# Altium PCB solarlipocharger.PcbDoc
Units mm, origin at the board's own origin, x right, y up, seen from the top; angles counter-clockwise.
Board outline 52.7 x 22.73 mm, 2 copper layers (Top Layer, Bottom Layer); 23 components, 15 nets, 70 pads, 27 vias.
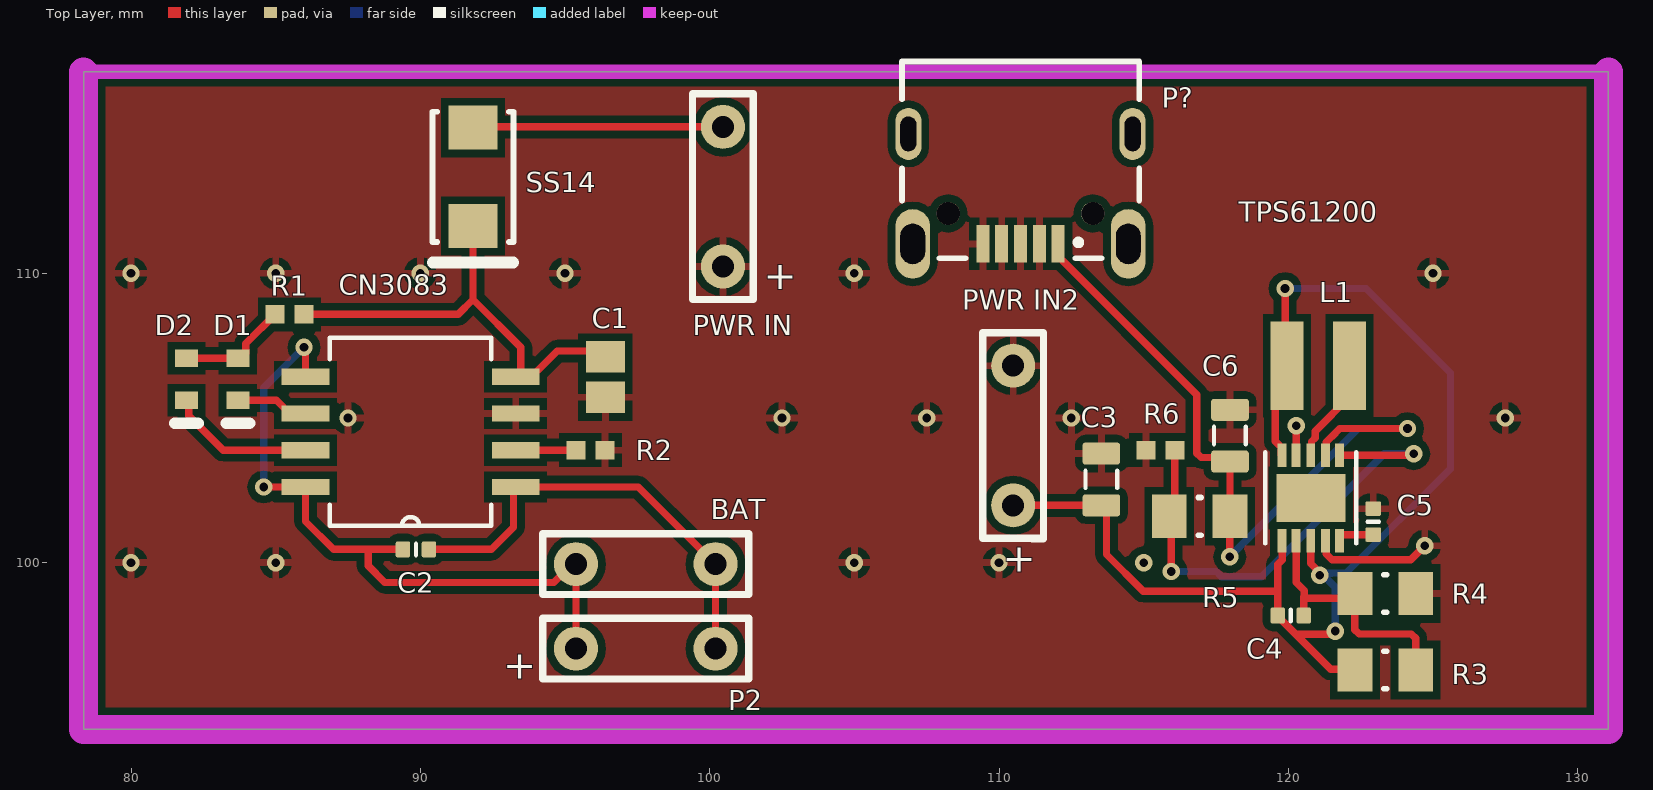
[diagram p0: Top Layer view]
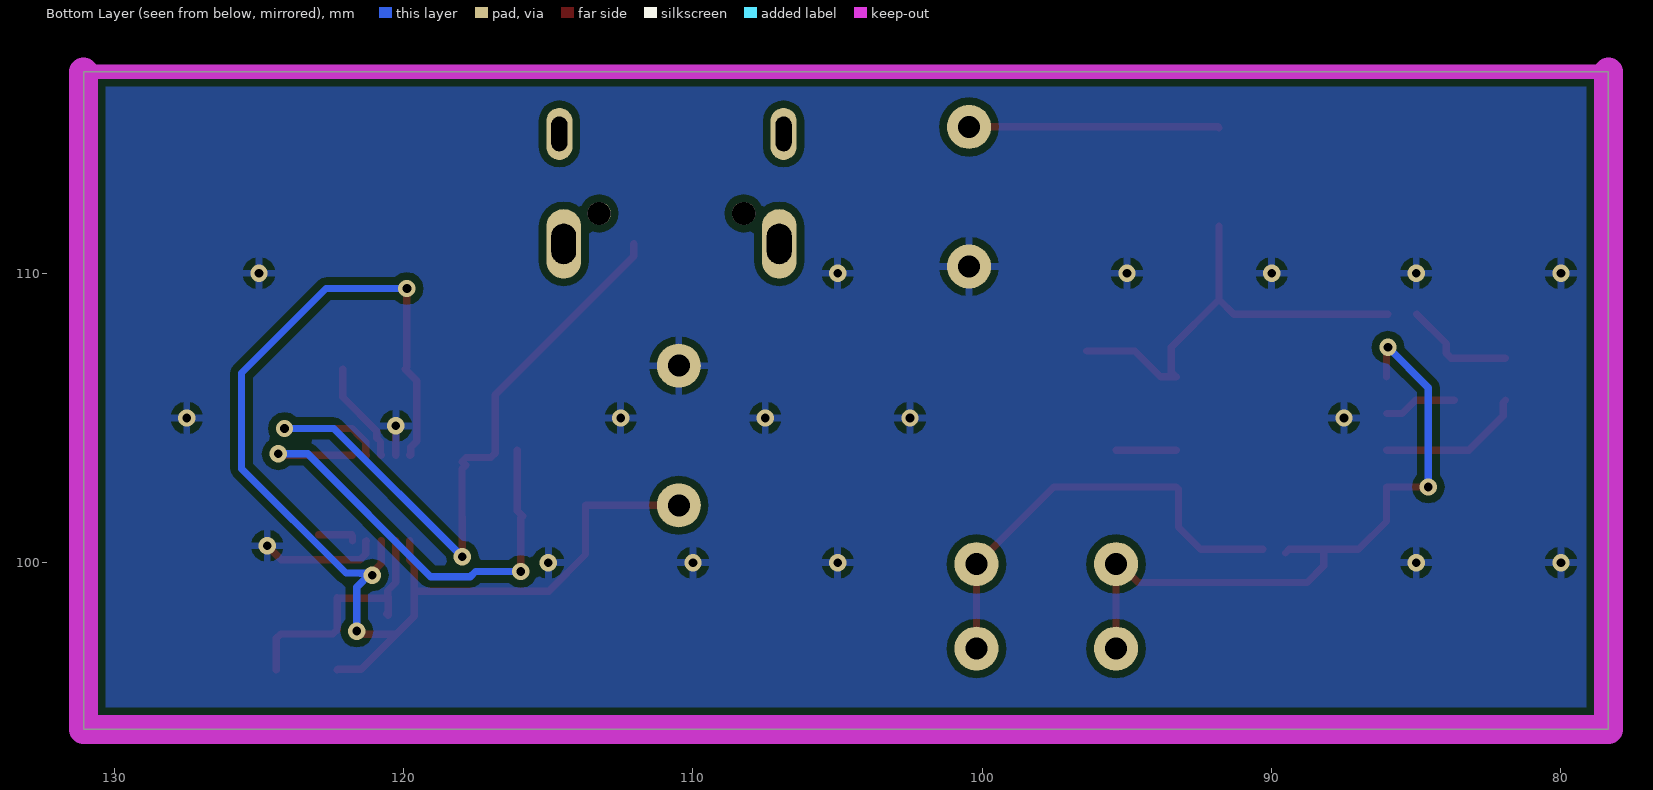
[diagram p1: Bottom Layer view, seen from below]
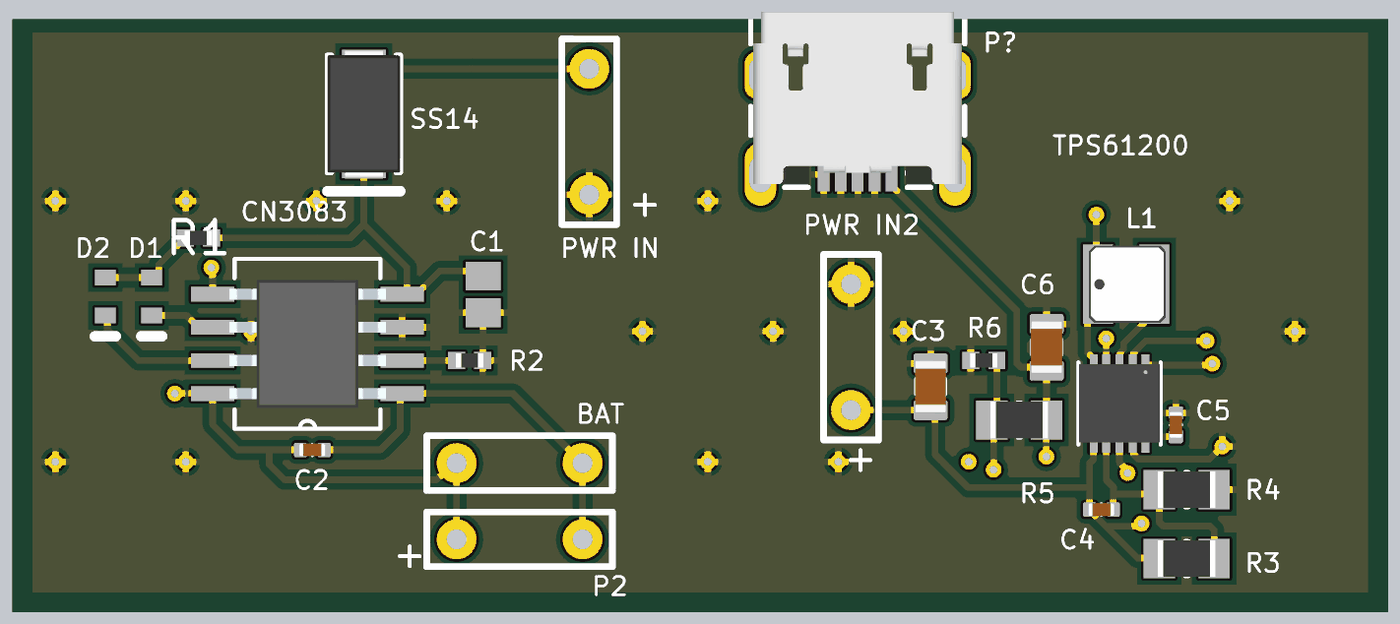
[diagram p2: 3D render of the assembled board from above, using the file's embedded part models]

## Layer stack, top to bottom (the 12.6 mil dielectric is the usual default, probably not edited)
Top Solder: solder mask 0.0102, Solder Resist, Dk 3.5
Top Layer: signal copper 0.0356
Dielectric 1: dielectric 0.32, FR-4, Dk 4.8
Bottom Layer: signal copper 0.0356
Bottom Solder: solder mask 0.0102, Solder Resist, Dk 3.5

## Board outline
78.359,94.234 131.064,94.234 131.064,116.967 78.359,116.967

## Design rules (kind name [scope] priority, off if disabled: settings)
Clearance [All] p1: gap=0.254 ignorepadtopadclearanceinfootprint=FALSE except(0: Arc-Hole Track-Hole SMDPad-Hole THPad-Hole Via-Hole Fill-Hole Poly-Hole Region-Hole Text-Hole; 0.127: Arc-Arc Arc-Track Arc-SMDPad Track-Track Track-SMDPad SMDPad-SMDPad)
PolygonConnect [All] p1: connectstyle=Relief reliefconductorwidth=0.254 reliefentries=4 polygonreliefangle="90 Angle" airgapwidth=0.254
RoutingVias [All] p1: holewidth=0.3 width=1.27 viastyle="Through Hole" minholewidth=0.3 minwidth=0.6 maxholewidth=0.711 maxwidth=0.6
SolderMaskExpansion [All] p1: expansion=0.102 istentingtop=FALSE
Width [All] p1: maxlimit=0.254 minlimit=0.254 preferedwidth=0.254
30 further rules are at their usual default settings.

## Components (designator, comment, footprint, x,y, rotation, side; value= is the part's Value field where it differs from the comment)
BAT "BAT" PWR 97.79,99.949 r0 top
C1 "08056D226MAT2A" CAPC2013X140X50LL20T25 96.393,106.415 r270 top
C2 "4.7 uF" "CAPACITOR 0402" 89.847,100.457 r0 top
C3 "10 uF" "CAPACITOR 0805" 113.538,102.881 r90 top
C4 "0.1 uF" "CAPACITOR 0402" 120.084,98.171 r0 top
C5 "0.1 uF" "CAPACITOR 0402" 122.936,101.415 r90 top
C6 "22 uF" "CAPACITOR 0805" 117.983,104.393 r90 top
CN3083 "CN3038" CN3083 89.662,104.648 r180 top
D1 "GREEN" "DIODE 0603" 83.693,106.336 r270 top
D2 "RED" "DIODE 0603" 81.915,106.336 r270 top
L1 "4.7 uF 1.2A" LPS3015 121.031,106.807 r0 top
P2 "PWR OUT" PWR 97.79,97.028 r0 top
P? "MICRO USB  PORT" "MICRO USB OUT" 110.744,114.173 r180 top
"PWR IN" "SOLAR PWR IN" PWR 100.457,112.649 r270 top
"PWR IN2" "BAT IN" PWR 110.49,104.394 r90 top
R1 "330" "RESISTOR 0402" 85.479,108.585 r180 top
R2 "3.6k" "RESISTOR 0402" 95.877,103.886 r0 top
R3 "2M" "RESISTOR 0805" 123.351,96.289 r0 top
R4 "220k" "RESISTOR 0805" 123.351,98.933 r0 top
R5 "1.2M" "RESISTOR 0805" 116.933,101.6 r180 top
R6 "220k" "RESISTOR 0402" 115.578,103.886 r180 top
SS14 "SS14 Diode" SS14 91.827,113.345 r270 top
TPS61200 "TPS61200" TPS61200 120.777,102.235 r270 top

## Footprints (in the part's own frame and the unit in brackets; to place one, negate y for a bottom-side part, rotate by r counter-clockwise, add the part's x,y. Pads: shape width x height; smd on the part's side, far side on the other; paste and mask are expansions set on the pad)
"CAPACITOR 0402" [mm]
  rrect25% 0.5x0.55 smd: 1(-0.45,0) 2(0.45,0)
  silkscreen extent 0,-0.2 0,0.2, body extent -0.5,-0.25 0.5,0.25, height 0.6
"CAPACITOR 0805" [mm]
  rrect25% 0.76x1.3 smd: 1(-0.9,0) 2(0.89,0)
  silkscreen extent -0.3,-0.55 0.3,0.55, body extent -1,-0.6 1,0.6, height 1.45
CAPC2013X140X50LL20T25 [mm] "Chip Capacitor, 2-Leads, Body 2.00x1.25mm, IPC High Density"
  rect 1.1x1.35 smd: 1(-0.7,0) 2(0.7,0)
  body extent -1.1,-0.72 1.1,0.72, height 1.4
CN3083 [mil]
  rect 65x22 smd: 1(-143,80) 2(-143,30) 3(-143,-20) 4(-143,-70) 5(143,-70) 6(143,-20) 7(143,30) 8(143,80)
  silkscreen extent -110,-123 110,133, body extent -118,-91 118,101, height 69
"DIODE 0603" [mm]
  rect 0.6x0.8 smd: 1(-0.725,0) 2(0.725,0)
  silkscreen extent 1.53,-0.4 1.53,0.4, body extent -0.8,-0.4 0.8,0.4, height 0.65
LPS3015 [mm]
  rect 1.14x3.05 smd: 1(-1.08,0) 2(1.08,0)
  body extent -1.43,-1.47 1.52,1.47, height 1.4
"MICRO USB OUT" [mm]
  rect 0.45x1.3 smd: 1(-1.3,3.154) 2(-0.65,3.154) 3(0,3.154) 4(0.65,3.154) 5(1.3,3.154)
  oval 1.2x2.4 hole 0.85 slot 1.4 at 90 deg: S1(-3.725,3.154) S2(3.725,3.154)
  oval 0.9x1.8 hole 0.55 slot 1.2 at 90 deg: S3(3.875,-0.646) S4(-3.875,-0.646)
  round 0.8 hole 0.8 unplated: ""(-2.5,2.104) ""(2.5,2.104)
  silkscreen extent -4.1,-3.15 4.1,3.65, body extent -4,-3.06 4,3.54, height 1.67
PWR [mil]
  round 60 hole 30: 1(-95,0) 2(95,0)
  silkscreen extent -140,-41 140,41
"RESISTOR 0402" [mm]
  rect 0.65x0.65 smd: 1(-0.5,0) 2(0.5,0)
  body extent -0.53,-0.28 0.53,0.28, height 0.4
"RESISTOR 0805" [mm]
  rect 1.2x1.5 smd: 1(-1.05,0) 2(1.05,0)
  silkscreen extent -0.05,-0.65 0.05,0.65, body extent -1.1,-0.7 1.1,0.7, height 0.5
SS14 [mm]
  rect 1.52x1.68 smd: 1(-1.688,-0.006) 2(1.712,-0.006)
  silkscreen extent -2.24,-1.41 2.97,1.39, body extent -2.46,-1.4 2.48,1.39, height 2.29
TPS61200 [mil]
  rect 32x12 smd: 1(-58,39) 2(-58,20) 3(-58,0) 4(-58,-20) 5(-58,-39) 6(58,-39) 7(58,-20) 8(58,0) 9(58,20) 10(58,39)
  rect 65x94 smd: 11(0,0)
  silkscreen extent -62,-62 62,62, body extent -59,-61 59,61, height 39

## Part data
C1: library part CMP-001-00083-1, "AVX         08056D226MAT2A.            CERAMIC CAPACITOR, 22UF, 6.3V, X5R, 20%, 0805, FULL REEL", Capacitance=22uF, Case Code (Imperial)=0805, Case Code (Metric)=2012, Dielectric=X5R, Dielectric Material=Ceramic, Insulation Resistance=10GR, Max Operating Temperature=85°C, Min Operating Temperature=-55°C, Package Quantity=1, Tolerance=20%, Voltage=6.3V
C2 C4 C5: library part "Capacitor 0402"
C3 C6: library part "Capacitor 0805"
D1 D2: library part "Diode 0603"
L1: library part Inductor, "LPS3015 - 222MRB"
"PWR IN2": library part "SOLAR PWR IN"
R1 R2 R6: library part "Resistor 0402"
R3 R4 R5: library part "Resistor 0805"

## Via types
v1: diameter 0.6, hole 0.3, Top Layer to Bottom Layer, 27 vias

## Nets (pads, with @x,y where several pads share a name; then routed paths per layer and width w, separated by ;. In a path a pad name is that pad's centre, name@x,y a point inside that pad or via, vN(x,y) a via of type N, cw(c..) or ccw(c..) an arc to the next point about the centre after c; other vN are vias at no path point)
GND: "PWR IN2.2" "PWR IN.2" C1.2 C3.2 C5.2 C6.2 CN3083.3 P?.2 P?.3 P?.4 P?.5 R2.2 R4.2 R6.2 TPS61200.4 TPS61200.9 | length 5.2
  Top Layer w0.254: TPS61200.4 v1(120.269,104.728) ; TPS61200.9 121.31,100.736 121.31,100.301 121.51,100.101 124.231,100.101 v1(124.714,100.584)
  other v1: 80,100 85,100 105,100 110,100 115,100 87.5,105 102.5,105 107.5,105 112.5,105 127.5,105 80,110 85,110 90,110 95,110 105,110 125,110
NetBAT_1: BAT.1 C2.1 CN3083.5 CN3083.8 P2.1 | length 24.2
  Top Layer w0.254: v1(84.582,102.616) CN3083.8 86.03,101.422 86.995,100.457 88.196,100.457 ; v1(85.979,107.442) 86.03,107.391 CN3083.5 ; C2.1@89.52,100.334 C2.1 88.196,100.457 ; P2.1 BAT.1 95.241,99.949 94.606,99.314 88.773,99.314 88.196,99.891 88.196,100.457
  Bottom Layer w0.254: v1(84.582,102.616) 84.582,106.045 v1(85.979,107.442)
NetBAT_2: BAT.2 C2.2 CN3083.1 P2.2 | length 15.6
  Top Layer w0.254: C2.2 92.456,100.457 93.218,101.219 93.218,102.54 CN3083.1 97.536,102.616 BAT.2 P2.2
NetC1_1: C1.1 CN3083.4 R1.1 SS14.2 | length 15.5
  Top Layer w0.254: R1.1 91.313,108.585 91.821,109.093 ; SS14.2 91.821,109.093 ; CN3083.4 CN3083.4@93.32,106.426 ; C1.1@96.393,107.315 94.729,107.315 93.84,106.426 CN3083.4@93.32,106.426 ; 91.821,109.093 93.472,107.442 93.472,106.578 CN3083.4@93.32,106.426
NetC3_1: "PWR IN2.1" C3.1 C4.1 L1.1 R3.1 TPS61200.5 TPS61200.6 TPS61200.8 | length 44.7
  Top Layer w0.254: 110.49,101.981 113.713,101.981 113.713,100.282 114.981,99.014 119.634,99.014 ; TPS61200.6 119.786,100.101 119.634,99.949 119.634,99.014 ; TPS61200.5 119.761,103.734 119.761,103.988 119.552,104.197 119.552,106.281 119.951,106.68 119.888,106.743 v1(119.888,109.474) ; TPS61200.8 120.777,99.971 121.087,99.661 v1(121.087,99.568) ; v1(121.622,97.635) 121.556,97.568 121.444,97.568 121.405,97.529 120.251,97.529 ; R3.1 122.279,96.311 121.469,96.311 120.251,97.529 ; 119.634,99.014 C4.1 119.634,98.146 120.251,97.529
  Bottom Layer w0.254: v1(119.888,109.474) 122.682,109.474 125.603,106.553 125.603,103.251 121.995,99.643 121.514,99.643 121.505,99.634 121.153,99.634 v1(121.087,99.568) ; v1@121.147,99.63 121.622,99.155 v1(121.622,97.635)
NetC4_2: C4.2 R3.2 R4.1 TPS61200.7 | length 9
  Top Layer w0.254: TPS61200.7 120.269,99.314 120.545,99.038 120.545,98.828 120.534,98.817 120.534,98.767 ; C4.2@120.595,98.232 C4.2 120.534,98.767 ; R3.2 124.401,97.387 124.252,97.536 122.45,97.536 122.301,97.685 122.301,98.783 122.285,98.767 120.534,98.767
NetC5_1: C5.1 TPS61200.10 | length 1.4
  Top Layer w0.254: TPS61200.10 121.768,100.94 121.793,100.965 C5.1
NetC6_1: C6.1 P?.1 R5.1 TPS61200.2 | length 25.2
  Top Layer w0.254: P?.1 112.044,110.594 116.84,105.798 116.84,103.781 116.989,103.632 117.844,103.632 C6.1 ; C6.1@117.856,103.366 117.983,103.24 R5.1 117.975,101.592 v1(117.975,100.198) ; TPS61200.2 121.31,103.734 121.31,104.169 121.51,104.369 121.514,104.369 121.779,104.634 v1(124.117,104.634)
  Bottom Layer w0.254: v1(117.975,100.198) 122.411,104.634 v1(124.117,104.634)
NetCN3083_2: CN3083.2 R2.1 | length 2.1
  Top Layer w0.254: CN3083.2 R2.1
NetCN3083_6: CN3083.6 D1.2 | length 2.5
  Top Layer w0.254: D1.2 85.029,105.611 85.484,105.156 CN3083.6
NetCN3083_7: CN3083.7 D2.2 | length 5.1
  Top Layer w0.254: D2.2 81.992,105.534 81.992,105.079 83.185,103.886 CN3083.7
NetD1_1: D1.1 D2.1 R1.2 | length 3.9
  Top Layer w0.254: D2.1 D1.1 83.793,107.061 83.966,107.234 83.966,107.572 R1.2
NetL1_2: L1.2 TPS61200.3 | length 3.5
  Top Layer w0.254: TPS61200.3 120.802,103.734 120.802,104.189 120.932,104.319 120.932,104.546 122.111,105.725 L1.2@122.111,106.68
"NetPWR IN_1": "PWR IN.1" SS14.1 | length 8.6
  Top Layer w0.254: SS14.1 91.85,115.062 100.457,115.062
NetR5_2: R5.2 R6.1 TPS61200.1 | length 17.1
  Top Layer w0.254: v1(115.951,99.695) 115.951,101.532 R5.2 116.078,101.795 R6.1 ; TPS61200.1 124.282,103.708 v1(124.333,103.759)
  Bottom Layer w0.254: v1(115.951,99.695) 117.515,99.695 117.693,99.517 119.075,99.517 123.317,103.759 v1(124.333,103.759)
pads on no net: P?. P?.S1 P?.S2 P?.S3 P?.S4 TPS61200.11

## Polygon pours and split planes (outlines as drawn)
GND on Top Layer "TOPLAYERGND" (solid, pour order 8): 78.359,94.234 131.064,94.234 131.064,116.967 78.359,116.967
GND on Bottom Layer "BOTTOMLAYERGND" (solid, pour order 9): 78.359,94.234 131.064,94.234 131.064,116.967 78.359,116.967

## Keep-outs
Keep-Out Layer:
  lines w0.5: 78.359,94.234 78.359,116.967 ; 78.359,94.234 131.064,94.234 ; 78.359,94.234 78.359,116.967 ; 78.359,94.234 131.064,94.234 ; 78.359,116.967 131.064,116.967 ; 131.064,94.234 131.064,116.967 ; 131.064,94.234 131.064,116.967
  lines w1: 78.359,116.967 78.359,94.234 131.064,94.234 131.064,116.967

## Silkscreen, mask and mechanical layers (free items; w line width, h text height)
Top Overlay:
  text "+" at 101.877,109.457 h1
  text "+" at 110.132,99.678 h1
  text "+" at 92.86,95.995 h1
